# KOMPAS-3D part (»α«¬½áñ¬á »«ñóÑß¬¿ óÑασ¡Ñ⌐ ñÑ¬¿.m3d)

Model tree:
1. Эскиз:1
2. Операция выдавливания:1
     Расстояние 1 = 3
3. Эскиз:2
4. Вырезать элемент выдавливания:1
     Толщина стенки 1 = 2; Расстояние 1 = 10
